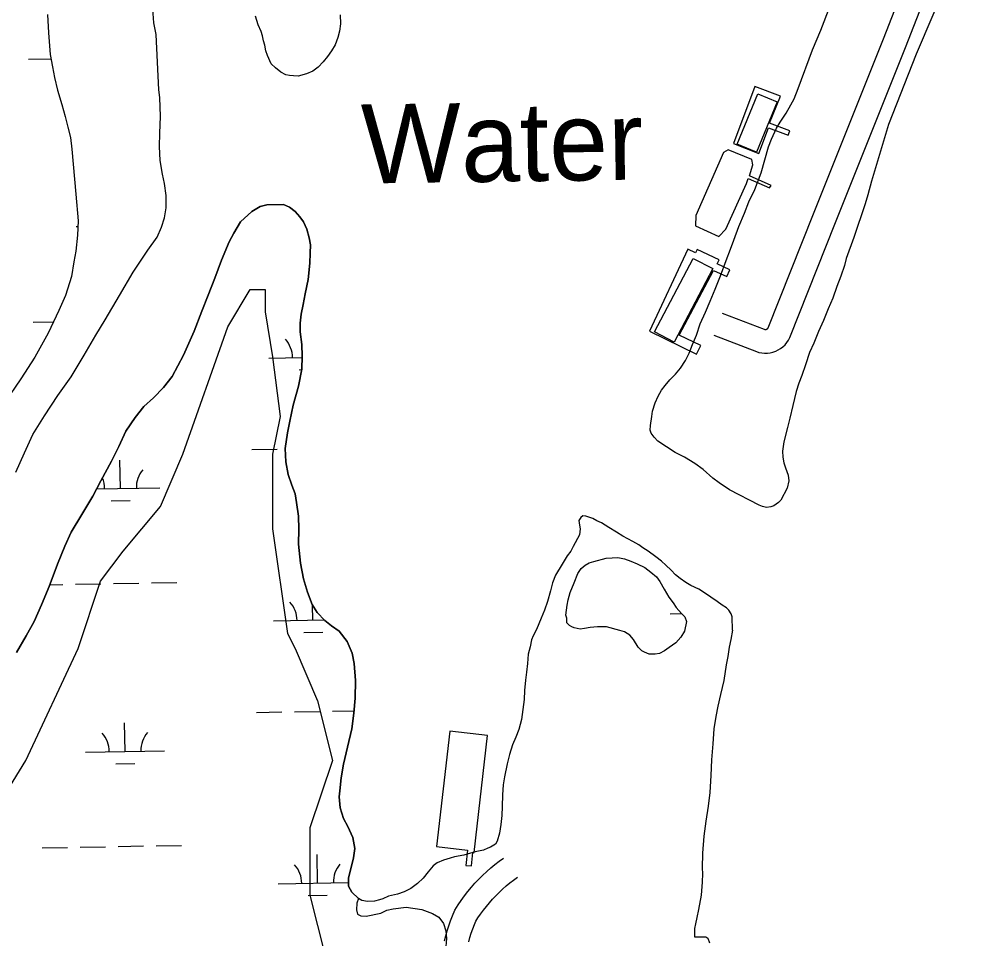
# Model space of a CAD drawing. Extents: x 3903937 to 3942190, y 260677 to 286651.
# Drawn here: x 3909185 to 3910391, y 276495 to 277659 of the extents above; entities that cross this region are included whole.
import ezdxf

# ---------------------------------------------------------------- set-up
doc = ezdxf.new("R2010")
doc.units = 0
for name, color, linetype in [('V-BLDG-OTLN', 7, 'Continuous'), ('V-CHAN-DOCK', 7, 'Continuous'), ('V-RIVR-IDEN', 7, 'Continuous'), ('V-ROAD-CNTR', 7, 'Continuous'), ('V-SITE-VEGE', 7, 'Continuous'), ('V-TOPO-SHOR', 7, 'Continuous'), ('V-WETL-SWMP', 7, 'Continuous')]:
    doc.layers.add(name, color=color, linetype=linetype)

msp = doc.modelspace()

# ---------------------------------------------------------------- linework, layer by layer
at = {"layer": 'V-BLDG-OTLN'}
for points in [[(3910117.4, 277490.5), (3910092.9, 277500.6), (3910119.2, 277564.3), (3910143.7, 277554.1)], [(3910013.2, 277250.1), (3909988.6, 277263.1), (3910037.5, 277356), (3910062.2, 277343)]]:
    msp.add_lwpolyline(points, close=True, dxfattribs=at)
at = {"layer": 'V-CHAN-DOCK'}
for points in [[(3910159.4, 277517.5), (3910133.9, 277527.1), (3910147.6, 277561.3), (3910115.5, 277573.7), (3910088.5, 277501.5), (3910120.3, 277488.6), (3910132.6, 277521.3), (3910157.3, 277512), (3910159.4, 277517.5)], [(3910078.6, 277393.1), (3910104.6, 277450.9), (3910107, 277457), (3910133.8, 277445.3), (3910135.9, 277448.4), (3910108.5, 277460.4), (3910112.7, 277474.5), (3910111.4, 277481.3), (3910081.6, 277493.5), (3910075.8, 277490.1), (3910040.8, 277410.2), (3910040.3, 277397), (3910069.8, 277383.8), (3910078.6, 277393.1)], [(3910083.7, 277341.4), (3910067.7, 277348.9), (3910070.2, 277354.3), (3910042.4, 277367.3), (3910040.4, 277363), (3910030.6, 277367.6), (3909982.1, 277263.9), (3910041.7, 277234.9), (3910047.1, 277245.9), (3910019.8, 277258.7), (3910063.2, 277340.8), (3910079.8, 277333.1), (3910083.7, 277341.4)], [(3909760.3, 276604.1), (3909777.4, 276752.2), (3909729.7, 276757.7), (3909712.8, 276611.6), (3909751.9, 276607.1), (3909749.7, 276587.9), (3909756.9, 276587.1), (3909758.8, 276604.3), (3909760.3, 276604.1)]]:
    msp.add_lwpolyline(points, dxfattribs=at)
at = {"layer": 'V-ROAD-CNTR'}
for points in [[(3910074, 277286.7), (3910127.2, 277266.4), (3910127.9, 277266.2), (3910128.3, 277266.1), (3910128.7, 277266.1), (3910129.1, 277266.1), (3910129.5, 277266.2), (3910129.9, 277266.3), (3910130.3, 277266.4), (3910130.7, 277266.6), (3910131, 277266.8), (3910131.3, 277267), (3910131.6, 277267.3), (3910131.9, 277267.6), (3910132.1, 277268), (3910132.3, 277268.3), (3910189.5, 277412.5), (3910278, 277633.8), (3910363.4, 277852.5)], [(3910063.3, 277258.7), (3910117.4, 277238.1), (3910120.5, 277237.1), (3910124, 277236.4), (3910127.6, 277236.1), (3910131.2, 277236.1), (3910134.8, 277236.6), (3910138.3, 277237.4), (3910141.7, 277238.6), (3910145, 277240.1), (3910148, 277242), (3910150.9, 277244.2), (3910153.5, 277246.7), (3910155.8, 277249.5), (3910157.8, 277252.4), (3910159.6, 277255.7), (3910217.4, 277401.4), (3910305.9, 277622.8), (3910391.2, 277841.2)], [(3909723, 276492.2), (3909724.5, 276498.7), (3909726.3, 276505.1), (3909728.2, 276511.5), (3909730.4, 276517.8), (3909732.8, 276524.1), (3909735.8, 276531.2), (3909740.1, 276537.9), (3909744, 276543.6), (3909748.1, 276549.3), (3909752.4, 276554.7), (3909756.8, 276560.1), (3909761.4, 276565.3), (3909766.2, 276570.3), (3909771.1, 276575.2), (3909776.2, 276580), (3909781.4, 276584.6), (3909786.7, 276589), (3909792.2, 276593.3), (3909797.6, 276597.2)], [(3909753.6, 276491.3), (3909755.1, 276496.8), (3909756.7, 276502.2), (3909758.6, 276507.6), (3909760.6, 276512.9), (3909762.4, 276517.2), (3909765.1, 276521.3), (3909768.5, 276526.3), (3909772.1, 276531.2), (3909775.8, 276535.9), (3909779.6, 276540.5), (3909783.6, 276545), (3909787.7, 276549.4), (3909792, 276553.7), (3909796.4, 276557.8), (3909800.9, 276561.8), (3909805.5, 276565.6), (3909810.3, 276569.3), (3909815.3, 276573)]]:
    msp.add_lwpolyline(points, dxfattribs=at)
at = {"layer": 'V-SITE-VEGE'}
msp.add_lwpolyline([(3909042, 276474.4), (3909193.3, 276720.5), (3909259.5, 276862.4), (3909287.9, 276947.5), (3909316.3, 276985.4), (3909363.6, 277042.2), (3909392, 277108.4), (3909448.7, 277269.2), (3909477.1, 277316.6), (3909496, 277316.6), (3909496, 277288.2), (3909505.4, 277231.4), (3909514.9, 277155.7), (3909505.4, 277108.4), (3909505.4, 277013.8), (3909524.4, 276881.3), (3909533.8, 276862.4), (3909562.2, 276796.1), (3909581.1, 276720.5), (3909552.7, 276635.3), (3909552.7, 276550.1), (3909581.1, 276436.6)], dxfattribs=at)
at = {"layer": 'V-TOPO-SHOR'}
for points in [[(3910360.3, 277710.8), (3910319.5, 277614.3), (3910284.2, 277525.3), (3910262.8, 277453.8), (3910258.2, 277436.5), (3910254.8, 277425), (3910240.6, 277382.3), (3910230.7, 277355.8), (3910228.8, 277347.1), (3910224.2, 277333.3), (3910219.2, 277320.3), (3910213.8, 277305.6), (3910208, 277292.2), (3910202.3, 277277.5), (3910195.7, 277263.3), (3910190, 277248.7), (3910184.6, 277236.8), (3910179.6, 277221.4), (3910174.6, 277207.6), (3910170.8, 277198.1), (3910167.7, 277187.4), (3910163.5, 277170), (3910159.4, 277153.8), (3910156.7, 277142), (3910152.2, 277123.8), (3910150.3, 277112), (3910150.8, 277104.5), (3910152, 277097.4), (3910154.1, 277090.8), (3910157.3, 277081.7), (3910158.2, 277074.6), (3910156.3, 277065.2), (3910148.2, 277050.1), (3910145.1, 277046.9), (3910139.2, 277042.9), (3910135.7, 277041.7), (3910130.1, 277040.9), (3910125, 277042), (3910120.7, 277043.9), (3910083.1, 277062.9), (3910070.4, 277071.8), (3910062.4, 277078), (3910050.1, 277088.9), (3910039.4, 277096.3), (3910026.3, 277104.5), (3910014.4, 277110.3), (3909992.6, 277124.6), (3909987.9, 277129.7), (3909984.3, 277134.8)], [(3909361.6, 277569.4), (3909358.1, 277639.3), (3909355.2, 277653.9), (3909353.9, 277672)], [(3909992.9, 277181.7), (3909997.1, 277189.3), (3910001.8, 277195.2), (3910008, 277202.4), (3910015, 277209.5), (3910021.3, 277217.1), (3910027.5, 277226.6), (3910032.5, 277236.1), (3910036.7, 277247.2), (3910041.4, 277259), (3910046.3, 277273.3), (3910052.9, 277287.9), (3910058.7, 277301.7), (3910065.2, 277317.2), (3910072.1, 277333.8), (3910079, 277353.2), (3910084.4, 277367.8), (3910088.6, 277379.2), (3910095.2, 277396.3), (3910102.1, 277413.3), (3910107.8, 277427.5), (3910115.2, 277443.3), (3910123.2, 277464.3), (3910128.2, 277480.5), (3910132.8, 277497.1), (3910136.6, 277507), (3910142.8, 277520.8), (3910147.4, 277528.3), (3910154.8, 277539.8), (3910161, 277550.5), (3910164.9, 277558), (3910170.3, 277571.1), (3910188.3, 277619.7), (3910198.7, 277644.6), (3910210.6, 277675.5)], [(3909590.7, 277664.3), (3909591.2, 277652.9), (3909590.1, 277643.4), (3909587.8, 277635.5), (3909584.4, 277626.4), (3909580.1, 277618.5), (3909574.7, 277611.4), (3909569.6, 277604.6), (3909563, 277597.8), (3909556.3, 277593.1), (3909548.5, 277589.4), (3909537.9, 277586.6), (3909532, 277586.9), (3909526.8, 277587.6), (3909522.1, 277588.4), (3909515.8, 277591.5), (3909509, 277597.3), (3909503.8, 277602.4), (3909499, 277612.6), (3909497, 277618.5), (3909495.7, 277625.9), (3909494.1, 277631.4), (3909492.5, 277637.7), (3909491.2, 277643.2), (3909487.2, 277651.5), (3909483.9, 277662.5)], [(3909371, 277435.7), (3909368.9, 277450.7), (3909366.4, 277462.5), (3909363.4, 277479.9), (3909362.5, 277497.6), (3909362.7, 277514.6), (3909363.7, 277535.5), (3909363, 277559.6), (3909361.6, 277569.4)], [(3909311.8, 277309.1), (3909328.9, 277338.5), (3909347.6, 277366.4), (3909359.3, 277382.7), (3909365.1, 277395.4), (3909368.9, 277407.2), (3909370.7, 277419.9), (3909371, 277435.7)], [(3909553.3, 277373.1), (3909551.6, 277381.8), (3909548.7, 277392.8), (3909544.7, 277402.2), (3909539.9, 277408.5), (3909533.9, 277415.2), (3909526.7, 277421), (3909519.2, 277424.1), (3909498.3, 277423.9), (3909489.6, 277421.5), (3909479, 277415.4), (3909464.9, 277402.3)], [(3909464.9, 277402.3), (3909456.4, 277388), (3909450.5, 277376.8), (3909440.9, 277353.8), (3909432.4, 277330.9), (3909423.9, 277309.4), (3909415.9, 277289.2), (3909406.2, 277263.9), (3909392.7, 277233.7), (3909378.4, 277206.7), (3909367.4, 277192.8), (3909354.9, 277179.6), (3909342.8, 277168.5), (3909331.5, 277154.5), (3909319.8, 277137.4), (3909310.9, 277118), (3909301.6, 277099.3), (3909288.4, 277074.7), (3909277.9, 277055.3), (3909264, 277031.8), (3909250.7, 277009.6), (3909242.6, 276991.7), (3909233.4, 276969.1), (3909223, 276940.6), (3909213.3, 276917.6), (3909203.7, 276896.6), (3909193.6, 276878.3), (3909181.5, 276857.2)], [(3909607.8, 276597.6), (3909609.3, 276609.1), (3909606.8, 276623.3), (3909600.7, 276637), (3909595.1, 276647.2), (3909591, 276660.6), (3909589.7, 276674.8), (3909590.4, 276682), (3909592.2, 276698.6), (3909595.2, 276716), (3909600.2, 276737.3), (3909605.5, 276760.7), (3909608.4, 276780.5), (3909609.8, 276799.4), (3909610.4, 276822), (3909608.6, 276843.3), (3909606.1, 276856.3), (3909599.6, 276871.2), (3909589.6, 276884.1), (3909580.1, 276891.2), (3909571.7, 276897.8), (3909561.8, 276908), (3909555.7, 276917.8), (3909549.7, 276933.5), (3909544.4, 276950.4), (3909540.6, 276970.2), (3909538, 276994.2), (3909538.6, 277013.2), (3909538.1, 277029.8), (3909535.5, 277047.1), (3909533.8, 277058.2), (3909529.8, 277068.8), (3909525.3, 277082.6), (3909522, 277098.7), (3909521.4, 277115.3), (3909524.4, 277135.1), (3909527.4, 277150.1), (3909531.5, 277170.3), (3909538, 277194.5), (3909542.6, 277215.8), (3909542.8, 277232.4), (3909542.6, 277247), (3909540.5, 277263.2), (3909540.4, 277273.9), (3909541.5, 277285.3), (3909544.1, 277297.6), (3909546.8, 277311), (3909550.5, 277329.2), (3909552.7, 277349.8), (3909553, 277362.8), (3909553.3, 277373.1)], [(3909180.9, 277085.5), (3909191.7, 277110.1), (3909202.1, 277133.1), (3909216.9, 277156.6), (3909234, 277182.4), (3909250.8, 277206.3), (3909267.1, 277233.7), (3909281.9, 277258.7), (3909293.9, 277278.2), (3909311.8, 277309.1)], [(3909984.3, 277134.8), (3909983.1, 277138.7), (3909983.4, 277144.6), (3909984.9, 277156), (3909986, 277162.7), (3909989.4, 277173.4), (3909992.9, 277181.7)], [(3910087.2, 276885.5), (3910086.7, 276902.4), (3910085.5, 276906), (3910082.6, 276910.7), (3910079.5, 276913.8), (3910073.9, 276917.3), (3910067.9, 276921.6), (3910059.6, 276927.1), (3910052.8, 276932.1), (3910044.5, 276937.2), (3910034.2, 276942.2), (3910028.2, 276945.7), (3910021, 276950.8), (3910015.1, 276955.5), (3910009.5, 276961.3), (3910002.7, 276967.6), (3909997.1, 276972.7), (3909990, 276978.5), (3909980.4, 276985.5), (3909973.7, 276989.8), (3909968.5, 276993.3), (3909960.9, 276997.6), (3909948.2, 277004.6), (3909940.3, 277009.6), (3909930.8, 277015.4), (3909921.6, 277021.3), (3909915.7, 277024), (3909910.5, 277026.7), (3909901.8, 277029.8), (3909897.8, 277030.1), (3909895.1, 277028.1), (3909893.5, 277025.7), (3909892.8, 277024.5), (3909893.6, 277018.6), (3909894.4, 277013.9), (3909893.7, 277006), (3909885.6, 276991.3), (3909882.5, 276985.7), (3909877.8, 276979.4), (3909871.6, 276969.1), (3909863.4, 276955.2), (3909859.6, 276945.6), (3909856.9, 276935.3), (3909853.1, 276921.9), (3909849.2, 276910.8), (3909845, 276900.5), (3909839.2, 276886.2), (3909834.9, 276878.3), (3909833, 276873.1), (3909831.1, 276864.4), (3909828.8, 276855.3), (3909827.8, 276843.4), (3909826.7, 276832.4), (3909825.2, 276822.1), (3909824.2, 276809), (3909823.5, 276797.6), (3909822, 276785.3), (3909820.2, 276772.3), (3909816.8, 276760), (3909812.9, 276750.1), (3909809, 276740.2), (3909805.2, 276728.3), (3909802.2, 276716.4), (3909798.8, 276699.8), (3909796.9, 276689.9), (3909796.2, 276677.3), (3909795.6, 276662.2), (3909795.3, 276650.8), (3909794.2, 276639.7), (3909792.4, 276628.6), (3909789.3, 276618.7), (3909787.4, 276614.8), (3909781.1, 276610.8), (3909777.5, 276609.5), (3909772, 276607.1), (3909761.8, 276605), (3909755.9, 276603.4), (3909747.2, 276600.9), (3909735.4, 276598.5), (3909729.9, 276597.2), (3909721.6, 276594.4), (3909713.7, 276591.1), (3909708.6, 276587.1), (3909702, 276579.6), (3909695.8, 276571.6), (3909688.7, 276564.8), (3909680.1, 276558.8), (3909671.8, 276554.4), (3909663.6, 276551.6), (3909652.2, 276548.7), (3909644.7, 276545.4), (3909640.7, 276544.2), (3909634.4, 276542.6), (3909625.4, 276542.1), (3909618.2, 276543.6), (3909614.3, 276545.9)], [(3910087.2, 276885.5), (3910085, 276873.6), (3910082.7, 276864.2), (3910081.3, 276852.4), (3910079, 276841.7), (3910076.1, 276821.7), (3910071.9, 276803.9), (3910068.5, 276789.3), (3910065.9, 276776.3), (3910063.7, 276760.6), (3910062.3, 276741.7), (3910060.5, 276721.6), (3910059.9, 276701.6), (3910058.6, 276680.3), (3910056.4, 276663), (3910053.4, 276643.7), (3910050.9, 276624.8), (3910049.1, 276603.2), (3910048.9, 276584.3), (3910049, 276577.6), (3910048.7, 276566.6), (3910047.3, 276550.1), (3910044.3, 276531.9), (3910042, 276522.1), (3910040.1, 276513.8), (3910039, 276507.9), (3910039.1, 276497.3), (3910053.3, 276497.4), (3910055.7, 276495.9), (3910058.1, 276490)], [(3909614.3, 276545.9), (3909605.5, 276554.1), (3909601.5, 276561.6), (3909601.4, 276571.9), (3909605.2, 276586.9), (3909607.8, 276597.6)]]:
    msp.add_lwpolyline(points, dxfattribs=at)
at = {"layer": 'V-WETL-SWMP'}
for p, q in [((3909220.6, 277664.7), (3909222, 277641.4)), ((3909222, 277641.4), (3909224.3, 277614.2)), ((3909196.6, 277608), (3909225.3, 277608.5)), ((3909224.3, 277614.2), (3909227.2, 277598.5)), ((3909227.2, 277598.5), (3909229.7, 277585.1)), ((3909229.7, 277585.1), (3909233.4, 277569)), ((3909233.4, 277569), (3909238.7, 277550.9)), ((3909238.7, 277550.9), (3909243.2, 277535.6)), ((3909243.2, 277535.6), (3909246.5, 277522.2)), ((3909246.5, 277522.2), (3909249.8, 277508.8)), ((3909249.8, 277508.8), (3909251.5, 277494.3)), ((3909251.5, 277494.3), (3909256.8, 277437.2)), ((3909256.8, 277437.2), (3909259.5, 277403.7)), ((3909489.6, 277421.5), (3909498.3, 277423.9)), ((3909498.3, 277423.9), (3909519.2, 277424.1)), ((3909519.2, 277424.1), (3909526.7, 277421)), ((3909464.9, 277402.3), (3909479, 277415.4)), ((3909479, 277415.4), (3909489.6, 277421.5)), ((3909526.7, 277421), (3909533.9, 277415.2)), ((3909533.9, 277415.2), (3909539.9, 277408.5)), ((3909259.5, 277403.7), (3909258.9, 277385.5)), ((3909456.4, 277388), (3909464.9, 277402.3)), ((3909539.9, 277408.5), (3909544.7, 277402.2)), ((3909544.7, 277402.2), (3909548.7, 277392.8)), ((3909257.2, 277396.4), (3909259.2, 277396.5)), ((3909450.5, 277376.8), (3909456.4, 277388)), ((3909548.7, 277392.8), (3909551.6, 277381.8)), ((3909258.9, 277385.5), (3909256.7, 277365)), ((3909440.9, 277353.8), (3909450.5, 277376.8)), ((3909551.6, 277381.8), (3909553.3, 277373.1)), ((3909256.7, 277365), (3909254.1, 277351.6)), ((3909553.3, 277373.1), (3909553, 277362.8)), ((3909254.1, 277351.6), (3909251.1, 277333)), ((3909432.4, 277330.9), (3909440.9, 277353.8)), ((3909553, 277362.8), (3909552.7, 277349.8)), ((3909552.7, 277349.8), (3909550.5, 277329.2)), ((3909251.1, 277333), (3909243.4, 277308.9)), ((3909423.9, 277309.4), (3909432.4, 277330.9)), ((3909550.5, 277329.2), (3909546.8, 277311)), ((3909243.4, 277308.9), (3909235.3, 277289.9)), ((3909415.8, 277289.2), (3909423.9, 277309.4)), ((3909546.8, 277311), (3909544.1, 277297.6)), ((3909544.1, 277297.6), (3909541.5, 277285.3)), ((3909235.3, 277289.9), (3909221.4, 277261.4)), ((3909406.2, 277263.9), (3909415.8, 277289.2)), ((3909541.5, 277285.3), (3909540.4, 277273.9)), ((3909202.5, 277275.4), (3909228.5, 277275.8)), ((3909540.4, 277273.9), (3909540.5, 277263.2)), ((3909221.4, 277261.4), (3909204.8, 277230.9)), ((3909392.7, 277233.7), (3909406.2, 277263.9)), ((3909540.5, 277263.2), (3909542.6, 277247)), ((3909542.6, 277247), (3909542.8, 277232.4)), ((3909204.8, 277230.9), (3909186.9, 277203.5)), ((3909378.3, 277206.7), (3909392.7, 277233.7)), ((3909542.8, 277232.4), (3909542.6, 277215.8)), ((3909500.6, 277229.9), (3909542.8, 277230.6)), ((3909542.6, 277215.8), (3909538, 277194.5)), ((3909538.9, 277215.1), (3909542.4, 277215.2)), ((3909186.9, 277203.5), (3909166.3, 277173.3)), ((3909367.4, 277192.8), (3909378.3, 277206.7)), ((3909354.9, 277179.6), (3909367.4, 277192.8)), ((3909538, 277194.5), (3909531.5, 277170.3)), ((3909342.8, 277168.5), (3909354.9, 277179.6)), ((3909331.5, 277154.5), (3909342.8, 277168.5)), ((3909531.5, 277170.3), (3909527.4, 277150.1)), ((3909319.8, 277137.4), (3909331.5, 277154.5)), ((3909527.4, 277150.1), (3909524.4, 277135.1)), ((3909310.9, 277118), (3909319.8, 277137.4)), ((3909524.4, 277135.1), (3909521.4, 277115.3)), ((3909301.6, 277099.3), (3909310.9, 277118)), ((3909479.3, 277114), (3909511.3, 277114.6)), ((3909521.4, 277115.3), (3909522, 277098.7)), ((3909288.4, 277074.7), (3909301.6, 277099.3)), ((3909313, 277064.7), (3909312.4, 277100.7)), ((3909522, 277098.7), (3909525.3, 277082.6)), ((3909277.9, 277055.3), (3909288.4, 277074.7)), ((3909525.3, 277082.6), (3909529.8, 277068.8)), ((3909282.7, 277064.2), (3909363, 277065.6)), ((3909529.8, 277068.8), (3909533.8, 277058.2)), ((3909264, 277031.8), (3909277.9, 277055.3)), ((3909533.8, 277058.2), (3909535.5, 277047.1)), ((3909301.3, 277049), (3909325.3, 277049.5)), ((3909535.5, 277047.1), (3909538.1, 277029.8)), ((3909250.7, 277009.6), (3909264, 277031.8)), ((3909538.1, 277029.8), (3909538.6, 277013.2)), ((3909242.6, 276991.7), (3909250.7, 277009.6)), ((3909538.6, 277013.2), (3909538, 276994.2)), ((3909233.4, 276969.1), (3909242.6, 276991.7)), ((3909538, 276994.2), (3909540.6, 276970.2)), ((3909223, 276940.6), (3909233.4, 276969.1)), ((3909540.6, 276970.2), (3909544.4, 276950.4)), ((3909223.9, 276943), (3909240.3, 276943.3)), ((3909256.3, 276943.6), (3909288.3, 276944.2)), ((3909304.3, 276944.4), (3909336.3, 276945)), ((3909352.3, 276945.3), (3909384.3, 276945.8)), ((3909544.4, 276950.4), (3909549.7, 276933.5)), ((3909213.3, 276917.6), (3909223, 276940.6)), ((3909549.7, 276933.5), (3909555.7, 276917.8)), ((3909203.7, 276896.6), (3909213.3, 276917.6)), ((3909555.7, 276917.8), (3909561.8, 276908)), ((3909556.5, 276898.1), (3909556.1, 276917.1)), ((3909561.8, 276908), (3909571.7, 276897.8)), ((3910008.3, 276906.1), (3910023, 276906.4)), ((3909193.6, 276878.3), (3909203.7, 276896.6)), ((3909506.5, 276897.2), (3909571.1, 276898.4)), ((3909571.7, 276897.8), (3909580.1, 276891.2)), ((3909544.8, 276882.5), (3909568.8, 276882.9)), ((3909580.1, 276891.2), (3909589.6, 276884.1)), ((3909589.6, 276884.1), (3909599.6, 276871.2)), ((3909181.5, 276857.2), (3909193.6, 276878.3)), ((3909599.6, 276871.2), (3909606.1, 276856.3)), ((3909606.1, 276856.3), (3909608.6, 276843.3)), ((3909608.6, 276843.3), (3909610.4, 276822)), ((3909610.4, 276822), (3909609.8, 276799.4)), ((3909609.8, 276799.4), (3909608.4, 276780.5)), ((3909485.1, 276781.4), (3909517.1, 276782)), ((3909533.1, 276782.3), (3909565.1, 276782.8)), ((3909581.1, 276783.1), (3909608.7, 276783.6)), ((3909608.4, 276780.5), (3909605.5, 276760.7)), ((3909318.9, 276732.1), (3909318.3, 276768.1)), ((3909605.5, 276760.7), (3909600.2, 276737.3)), ((3909600.2, 276737.3), (3909595.2, 276716)), ((3909268.9, 276731.2), (3909368.9, 276732.9)), ((3909307.2, 276716.4), (3909331.2, 276716.8)), ((3909595.2, 276716), (3909592.2, 276698.6)), ((3909592.2, 276698.6), (3909590.4, 276682)), ((3909590.4, 276682), (3909589.7, 276674.8)), ((3909589.7, 276674.8), (3909591, 276660.6)), ((3909591, 276660.6), (3909595.1, 276647.2)), ((3909595.1, 276647.2), (3909600.7, 276637)), ((3909600.7, 276637), (3909606.8, 276623.3)), ((3909606.8, 276623.3), (3909609.3, 276609.1)), ((3909214.2, 276610.1), (3909246.2, 276610.7)), ((3909262.2, 276611), (3909294.2, 276611.5)), ((3909310.2, 276611.8), (3909342.2, 276612.4)), ((3909358.2, 276612.7), (3909390.2, 276613.2)), ((3909609.3, 276609.1), (3909607.8, 276597.6)), ((3909562.3, 276565.5), (3909561.7, 276601.5)), ((3909607.8, 276597.6), (3909605.2, 276586.9)), ((3909605.2, 276586.9), (3909601.4, 276571.9)), ((3909601.4, 276571.9), (3909601.5, 276561.6)), ((3909512.3, 276564.6), (3909601.4, 276566.2)), ((3909601.5, 276561.6), (3909605.5, 276554.1)), ((3909550.6, 276549.9), (3909574.6, 276550.3)), ((3909605.5, 276554.1), (3909614.3, 276545.9)), ((3909614.3, 276545.9), (3909612, 276540.2)), ((3909612, 276540.2), (3909611.7, 276531.5)), ((3909611.7, 276531.5), (3909612.9, 276526)), ((3909649.8, 276531.1), (3909658, 276532.8)), ((3909658, 276532.8), (3909674.5, 276534.9)), ((3909674.5, 276534.9), (3909694.2, 276531.9)), ((3909694.2, 276531.9), (3909707.6, 276527)), ((3909612.9, 276526), (3909617.2, 276524.1)), ((3909617.2, 276524.1), (3909623.9, 276523.4)), ((3909623.9, 276523.4), (3909642.4, 276527.5)), ((3909642.4, 276527.5), (3909649.8, 276531.1)), ((3909707.6, 276527), (3909715.5, 276522.3)), ((3909715.5, 276522.3), (3909721.5, 276514.5)), ((3909721.5, 276514.5), (3909724.4, 276505.1)), ((3909725.2, 276495.3), (3909724.2, 276480.3)), ((3909724.4, 276505.1), (3909725.2, 276495.3))]:
    msp.add_line(p, q, dxfattribs=at)
msp.add_lwpolyline([(3909944.8, 276885.3), (3909927.8, 276889.8), (3909916.4, 276889.7), (3909906.9, 276888.9), (3909899.8, 276887.6), (3909894.3, 276886.8), (3909886.8, 276888.3), (3909884, 276889.8), (3909880.8, 276891.4), (3909879.6, 276892.5), (3909877.6, 276894.9), (3909877.5, 276900.8), (3909876.3, 276904.3), (3909877.8, 276917), (3909879.3, 276923.7), (3909882, 276933.2), (3909887, 276945.5), (3909891.6, 276957.4), (3909895.5, 276963.4), (3909900.6, 276967.8), (3909905.7, 276970.6), (3909911.6, 276972.6), (3909927.3, 276976.7), (3909934.8, 276977.2), (3909942, 276977.3), (3909950.3, 276975.8), (3909958.6, 276972.7), (3909966.5, 276969.6), (3909976.4, 276965), (3909984, 276959.1), (3909990.8, 276952.9), (3909995.2, 276947), (3910000.8, 276937.2), (3910006.4, 276927.3), (3910012, 276919.9), (3910016, 276914), (3910022.8, 276906.6), (3910026.8, 276902.3), (3910028.8, 276896.4), (3910026.6, 276884.1), (3910021.9, 276876.6), (3910015.3, 276869.4), (3910007, 276863.4), (3910001.2, 276859.4), (3909994.9, 276856.1), (3909989.4, 276855.3), (3909981.8, 276855.2), (3909975.9, 276857.5), (3909972.3, 276859.5), (3909967.9, 276863.8), (3909961.9, 276873.6), (3909957.1, 276879.1), (3909950.4, 276883.4)], close=True, dxfattribs=at)
for centre, start, end in [((3909495.4, 277230.3), 0.2366, 41.7802), ((3909368.3, 277066.1), 140.2366, 181.7802), ((3909257.8, 277064.2), 0.2366, 23.1698), ((3909501.2, 276897.6), 0.2366, 41.7802), ((3909263.7, 276731.6), 0.2366, 41.7802), ((3909374.1, 276733.5), 140.2366, 181.7802), ((3909507.1, 276565), 0.2366, 41.7802), ((3909617.6, 276567), 140.2366, 181.7802)]:
    msp.add_arc(centre, 35.2, start, end, dxfattribs=at)

# ---------------------------------------------------------------- texts
at = {"layer": 'V-RIVR-IDEN'}
msp.add_text('Water', height=100, rotation=0.8184, dxfattribs=at).set_placement((3909618.1, 277450.7))

doc.saveas('drawing.dxf')
